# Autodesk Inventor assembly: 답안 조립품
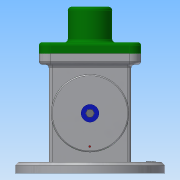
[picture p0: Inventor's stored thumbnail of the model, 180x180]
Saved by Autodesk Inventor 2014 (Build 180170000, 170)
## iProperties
Created: 2019-08
Part Number: 답안 조립품
Document SubType Name: Assembly
Designer: net
Author: net
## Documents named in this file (18)
- C:\Users\net\Desktop\490804V1036\답안 조립품.iam
- C:\Users\net\Desktop\490804V1036\본체.ipt
- C:\Users\net\Desktop\490804V1036\편심축.ipt
- C:\Users\net\Desktop\490804V1036\키 4 x 4 x 12.ipt
- C:\Users\net\Desktop\490804V1036\뒤커버.ipt
- C:\Users\net\Desktop\490804V1036\앞커버.ipt
- C:\Users\net\Desktop\490804V1036\볼트 M4 x 8.ipt
- C:\Users\net\Desktop\490804V1036\와셔 4x16.ipt
- C:\Users\net\Desktop\490804V1036\볼트 M4 x 10.ipt
- C:\Users\net\Desktop\490804V1036\V-벨트풀리.ipt
- C:\Users\net\Desktop\490804V1036\오일 실 17 30 8.ipt
- C:\Users\net\Desktop\490804V1036\베어링 17 x 40 x 12.ipt
- C:\Users\net\Desktop\490804V1036\덮개.ipt
- C:\Users\net\Desktop\490804V1036\슬라이더.ipt
- C:\Users\net\Desktop\490804V1036\클레비스 핀 6 x 22.ipt
- 클레비스 핀 6 x 22.ipt
- C:\Users\net\Desktop\490804V1036\링크.ipt
- C:\Users\net\Desktop\490804V1036\E-링.ipt
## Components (2 placed, 2 different names)
1. V-벨트풀리:1
2. E-링:1
